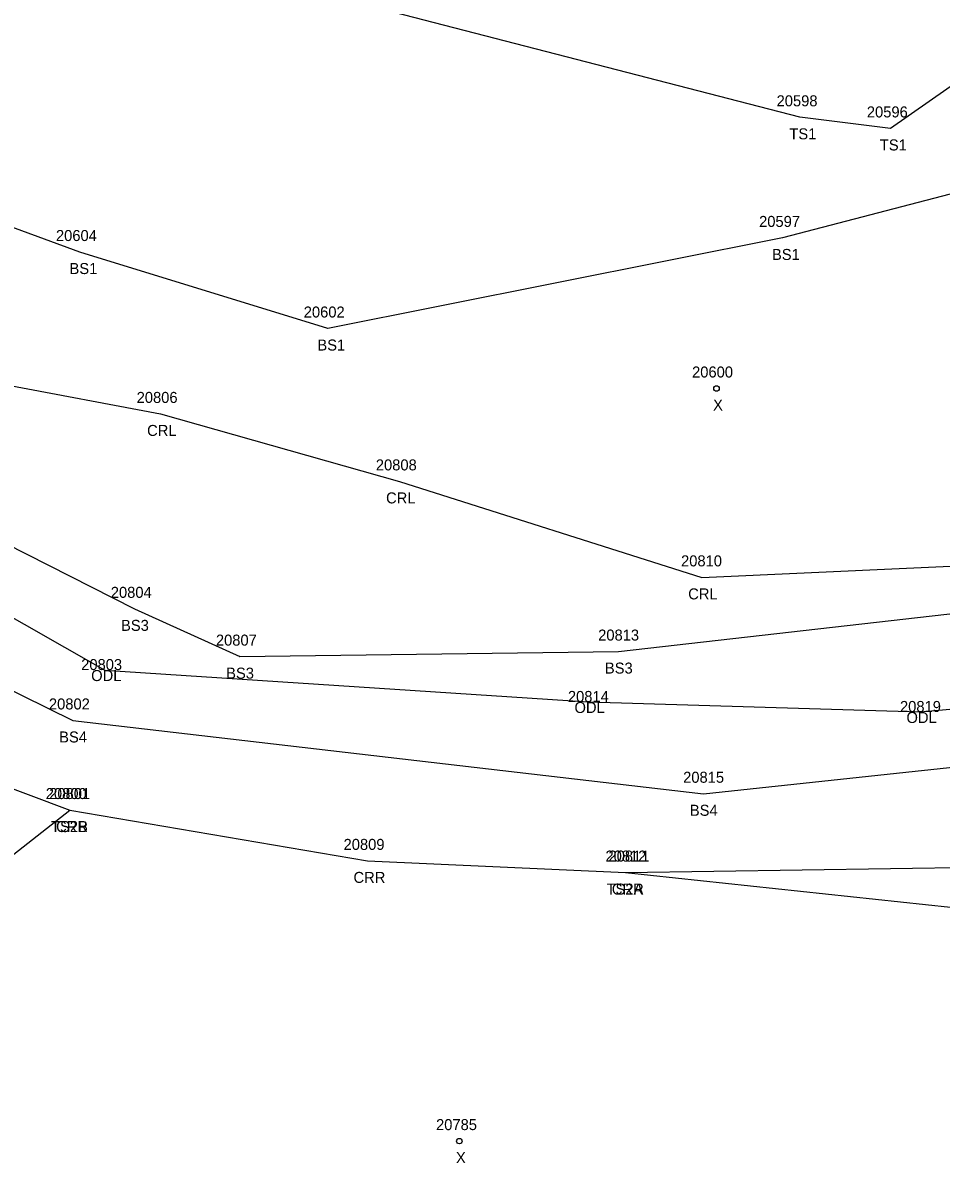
# Model space of a CAD drawing. Extents: x 1813127 to 1818290, y 1178171 to 1179900.
# Drawn here: x 1813568.5 to 1813651.9, y 1178635.7 to 1178739.3 of the extents above; entities that cross this region are included whole.
import ezdxf

# ---------------------------------------------------------------- set-up
doc = ezdxf.new("R2010")
doc.units = 0
for name, color, linetype in [('RD_DTM_BkLn2', 7, 'Continuous'), ('RD_EX_H2O', 7, 'Continuous'), ('RD_EX_H2O_txCode', 7, 'Continuous'), ('RD_SMD_Locator', 7, 'Continuous'), ('RD_SMD_Misc', 7, 'Continuous')]:
    doc.layers.add(name, color=color, linetype=linetype)

msp = doc.modelspace()

# ---------------------------------------------------------------- linework, layer by layer
at = {"layer": 'RD_DTM_BkLn2'}
for points in [[(1813728.98, 1178703.48), (1813680.74, 1178720.54), (1813670.9, 1178725.8), (1813665.35, 1178733.78), (1813654.36, 1178734.63), (1813647.32, 1178729.73), (1813639.1, 1178730.74), (1813591.11, 1178743.16), (1813543.28, 1178751.57), (1813511.7, 1178756.57), (1813494.92, 1178760.32), (1813445.74, 1178769.42), (1813422.91, 1178772.94), (1813422.78, 1178770.34)], [(1813501.61, 1178700.78), (1813535.62, 1178707.92), (1813578.65, 1178686.08), (1813588.2, 1178681.74), (1813622.61, 1178682.2), (1813653.79, 1178685.74), (1813685.17, 1178685.29), (1813723.1, 1178689.85), (1813736.83, 1178692.71), (1813771.26, 1178719.75), (1813784.46, 1178726.39), (1813801.14, 1178736.57), (1813819.08, 1178738.18), (1813840.25, 1178734.78), (1813848.44, 1178735.38), (1813862.15, 1178734.12), (1813885.61, 1178732.56), (1813903.34, 1178733.15)], [(1813719.9, 1178693.61), (1813672.18, 1178710.76), (1813660.65, 1178725.82), (1813637.51, 1178719.78), (1813596.2, 1178711.55), (1813573.69, 1178718.5), (1813539.15, 1178731.18), (1813521.54, 1178735.83), (1813479.61, 1178734.97)], [(1813494.55, 1178680.43), (1813533.86, 1178695.27), (1813573.03, 1178675.94), (1813630.33, 1178669.28), (1813656.92, 1178672.11), (1813691.39, 1178675.03), (1813721.31, 1178671.27), (1813738.7, 1178671.81), (1813780.2, 1178710.54), (1813805.93, 1178727.26), (1813819.91, 1178727.35), (1813841.4, 1178723.71), (1813860.66, 1178719.9), (1813869.89, 1178724.9), (1813872.35, 1178725.71), (1813884.47, 1178724.42), (1813903.61, 1178724.04)], [(1813499.93, 1178646.84), (1813530.8, 1178647.58), (1813558.17, 1178656.33), (1813572.78, 1178667.8)], [(1813623.26, 1178662.12), (1813655.04, 1178658.73), (1813668.37, 1178660.89), (1813682.02, 1178658.15), (1813729.97, 1178653.08)]]:
    msp.add_lwpolyline(points, dxfattribs=at)
at = {"layer": 'RD_EX_H2O'}
for points in [[(1813497.15, 1178691.5), (1813535.61, 1178703.5), (1813575.96, 1178680.52), (1813619.86, 1178677.62), (1813650.02, 1178676.71), (1813688.26, 1178680.15), (1813722.87, 1178676.67), (1813738.45, 1178684.24), (1813776.33, 1178715.9), (1813785.2, 1178724.07), (1813802.21, 1178734.6), (1813820.03, 1178732.78), (1813837.63, 1178729.78), (1813857.38, 1178730.32)], [(1813499.62, 1178706.37), (1813533.11, 1178716.31), (1813566.87, 1178706.45), (1813581.02, 1178703.79), (1813602.73, 1178697.66), (1813630.18, 1178688.94), (1813658.74, 1178690.22), (1813683.52, 1178690.56), (1813719.9, 1178693.61)], [(1813494.93, 1178677.14), (1813538.08, 1178685.02), (1813548.67, 1178684.4), (1813554.06, 1178674.83), (1813572.78, 1178667.8), (1813599.8, 1178663.18), (1813623.26, 1178662.12), (1813655.35, 1178662.6), (1813687.65, 1178668.53), (1813720.68, 1178667.78), (1813740.16, 1178669.89)]]:
    msp.add_lwpolyline(points, dxfattribs=at)
at = {"layer": 'RD_SMD_Locator'}
for centre, radius in [((1813639.1, 1178730.74), 0.001), ((1813647.32, 1178729.73), 0.001), ((1813637.51, 1178719.78), 0.001), ((1813573.69, 1178718.5), 0.001), ((1813596.2, 1178711.55), 0.001), ((1813631.52, 1178706.1), 0.25), ((1813581.02, 1178703.79), 0.001), ((1813602.73, 1178697.66), 0.001), ((1813630.18, 1178688.94), 0.001), ((1813578.65, 1178686.08), 0.001), ((1813622.61, 1178682.2), 0.001), ((1813588.2, 1178681.74), 0.001), ((1813575.96, 1178680.52), 0.001), ((1813619.86, 1178677.62), 0.001), ((1813650.02, 1178676.71), 0.001), ((1813573.03, 1178675.94), 0.001), ((1813630.33, 1178669.28), 0.001), ((1813572.78, 1178667.8), 0.001), ((1813572.78, 1178667.8), 0.001), ((1813599.8, 1178663.18), 0.001), ((1813623.26, 1178662.12), 0.001), ((1813623.26, 1178662.12), 0.001), ((1813608.16, 1178637.72), 0.25)]:
    msp.add_circle(centre, radius, dxfattribs=at)

# ---------------------------------------------------------------- texts
at = {"layer": 'RD_EX_H2O_txCode'}
for s, p in [('20806', (1813578.84, 1178704.79)), ('CRL', (1813579.79, 1178701.79)), ('20808', (1813600.57, 1178698.66)), ('CRL', (1813601.5, 1178695.66)), ('20810', (1813628.3, 1178689.94)), ('CRL', (1813628.95, 1178686.94)), ('20803', (1813573.8, 1178680.52)), ('ODL', (1813574.71, 1178679.52)), ('20814', (1813618.02, 1178677.62)), ('ODL', (1813618.62, 1178676.62)), ('20819', (1813648.19, 1178676.71)), ('ODL', (1813648.78, 1178675.71)), ('20800', (1813570.58, 1178668.8)), ('CRR', (1813571.52, 1178665.8)), ('20809', (1813597.64, 1178664.18)), ('20811', (1813621.71, 1178663.12)), ('CRR', (1813598.54, 1178661.18)), ('CRR', (1813622.01, 1178660.12))]:
    msp.add_text(s, height=1, dxfattribs=at).set_placement(p)
at = {"layer": 'RD_SMD_Misc'}
for s, p in [('20598', (1813636.98, 1178731.74)), ('20596', (1813645.18, 1178730.73)), ('TS1', (1813638.14, 1178728.74)), ('TS1', (1813646.36, 1178727.73)), ('20597', (1813635.39, 1178720.78)), ('20604', (1813571.51, 1178719.5)), ('BS1', (1813636.56, 1178717.78)), ('BS1', (1813572.74, 1178716.5)), ('20602', (1813594.02, 1178712.55)), ('BS1', (1813595.26, 1178709.55)), ('20600', (1813629.3, 1178707.1)), ('X', (1813631.21, 1178704.1)), ('20804', (1813576.49, 1178687.08)), ('BS3', (1813577.42, 1178684.08)), ('20807', (1813586.04, 1178682.74)), ('20813', (1813620.77, 1178683.2)), ('BS3', (1813621.38, 1178680.2)), ('BS3', (1813586.97, 1178679.74)), ('20802', (1813570.87, 1178676.94)), ('BS4', (1813571.8, 1178673.94)), ('20815', (1813628.49, 1178670.28)), ('20801', (1813570.9, 1178668.8)), ('BS4', (1813629.1, 1178667.28)), ('TS2B', (1813571.06, 1178665.8)), ('20812', (1813621.43, 1178663.12)), ('TS2A', (1813621.53, 1178660.12)), ('20785', (1813606.04, 1178638.72)), ('X', (1813607.85, 1178635.72))]:
    msp.add_text(s, height=1, dxfattribs=at).set_placement(p)

doc.saveas('drawing.dxf')
